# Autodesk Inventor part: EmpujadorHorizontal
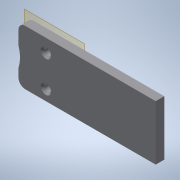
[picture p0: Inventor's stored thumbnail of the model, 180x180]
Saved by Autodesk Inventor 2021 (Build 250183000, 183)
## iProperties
Created: 2021-02
Part Number: EmpujadorHorizontal
Material: Genérico
Document SubType Name: Modeling
Designer: ATOUZA
Density: 1 g/cm^3
Appearance: Valor por defecto
Author: ATOUZA
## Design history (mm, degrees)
node "Plano de trabajo1"
sketch "Boceto1"
  geometry: L1 (-40, 16)-(40, 16); L2 (40, 16)-(40, -16); L3 (40, -16)-(-40, -16); L4 (-40, -16)-(-40, 16); L5 (-40, 16)-(40, -16); L6 (40, 16)-(-40, -16); L7 (-40, 0)-(-32, 0); L8 (-32, 0)-(-32, -16); L9 (-32, 0)-(-32, 16); 3 further points
  constraints: 18 end point, 5 midpoint, 3 point on line, 2 horizontal, 2 parallel, 2 perpendicular
  dimensions: "d13" = 80 distance of L2.end L3.end; "d14" = 32 distance of L1.end L2.end; "d15" = 8 distance of L7.start L7.end
extrude "Extrusión1" new body sketch "Boceto1" distance "d3" = 5; taper "d4" = 0 deg
sketch "Boceto3"
  geometry: L1 (40, 16)-(40, -16) reference; L2 (40, 0)-(32, 0); L3 (32, 0)-(32, -16); L4 (32, 0)-(32, 16); L5 (-40, 16)-(40, 16) reference; 3 further points
  constraints: 6 end point, 3 midpoint, 1 horizontal, 1 perpendicular, 1 point on line, 1 vertical
  dimensions: "d16" = 8 distance of L2.start L2.end
hole "Agujero2" sketch "Boceto3" at (32, -8), (32, 8) diameter "d17" = 4; stored, may be unused: countersink angle "d21" = 90 deg, drill point angle "d23" = 118 deg; dims "d18" = 6, "d19" = 6, "d20" = 2, "d22" = 18
fillet "Empalme1" dims "d24" = 4
node "Sólido1"
